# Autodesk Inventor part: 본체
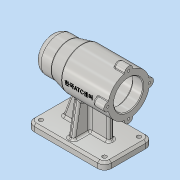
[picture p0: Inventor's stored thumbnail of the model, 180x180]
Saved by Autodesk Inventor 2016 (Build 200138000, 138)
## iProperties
Created: 2019-07
Part Number: 본체
Material: 알루미늄 6061
Document SubType Name: Modeling
Designer: Administrator
Density: 2.7 g/cm^3
Appearance: 알루미늄 - 평지
Mass: 644.388 g
Surface Area: 654.083 cm^2
Volume: 238.662 cm^3
Author: Administrator
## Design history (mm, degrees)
sketch "스케치1"
  geometry: L1 (56, 0)-(-56, 0); L2 (56, 0)-(56, 25); L3 (56, 25)-(31, 25); L4 (31, 25)-(11, 30); L5 (11, 30)-(-56, 30); L6 (-56, 30)-(-56, 21); L7 (-56, 21)-(-41, 21); L8 (-41, 21)-(-41, 24); L9 (-41, 24)-(13, 24); L10 (13, 24)-(13, 21); L11 (13, 21)-(25, 21); L12 (25, 21)-(25, 17.5); L13 (25, 17.5)-(43, 17.5); L14 (43, 17.5)-(43, 16); L15 (43, 16)-(47, 16); L16 (47, 16)-(47, 10.5); L17 (47, 10.5)-(50, 10.5); L18 (50, 10.5)-(50, 0); L19 (-56, 21)-(-56, 0); 2 further points
  constraints: 38 end point, 16 perpendicular, 1 coincident, 1 horizontal, 1 midpoint, 1 parallel, 1 point on line, 1 vertical
  dimensions: "d0" = 112 distance of L1.start L1.end; "d1" = 25 distance of L2.end L3.end; "d2" = 45 distance from line of L2 L4.end; "d3" = 60 diameter of L5 L1; "d4" = 50 diameter of L3 L1; "d5" = 3 distance between parallel lines of L18 L16; "d6" = 4 distance between parallel lines of L16 L14; "d7" = 18 distance between parallel lines of L12 L14; "d8" = 12 distance between parallel lines of L10 L12; "d9" = 54 distance between parallel lines of L8 L10; "d10" = 15 distance between parallel lines of L6 L8; "d11" = 42 diameter of L7 L1; "d12" = 48 diameter of L9 L1; "d13" = 21 diameter of L17 L1; "d14" = 32 diameter of L15 L1; "d15" = 35 diameter of L13 L1; "d16" = 42 diameter of L11 L1
revolve "회전1" sketch "스케치1" stored, may be unused: angle "d17" = 90 deg
node "작업 평면1"
sketch "스케치2"
  geometry: L1 (-56, -35)-(56, -35); L2 (56, -35)-(56, 35); L3 (56, 35)-(-56, 35); L4 (-56, 35)-(-56, -35); L5 (-56, -35)-(56, 35); L6 (56, -35)-(-56, 35); 1 further point
  constraints: 12 end point, 2 midpoint, 2 parallel, 1 horizontal, 1 perpendicular
  dimensions: "d19" = 112 distance of L3.end L2.end; "d20" = 70 distance of L2.end L1.end
extrude "돌출1" join sketch "스케치2" distance "d21" = 10; taper "d22" = 0 deg
sketch "스케치3"
  geometry: L1 (-56, -70)-(56, -70) reference; L2 (-31, -70)-(-31, -25.137); L3 (-31, -25.137)-(19.671, -25.137); L4 (19.671, -25.137)-(36, -70); L5 (56, -80)-(56, -70) reference; L6 (-56, -80)-(-56, -70) reference; 1 further point
  constraints: 6 end point, 2 point on line, 1 perpendicular, 1 vertical
  dimensions: "d23" = 20 distance from line of L5 L4.end; "d24" = 25 distance between parallel lines of L6 L2; "d25" = 110 deg angle of L1 L4; "d26" = 50.67136 distance of L2.end L3.end
extrude "돌출2" join sketch "스케치3" stored distance "d27" = 8; taper "d28" = 0 deg
sketch "스케치4"
  geometry: L1 (35, -70)-(-35, -70) reference; L2 (-28, -70)-(-19.654, -22.666); L3 (-35, -80)-(-35, -70) reference; 2 further points
  constraints: 2 end point, 1 point on line, 2 other
  dimensions: "d29" = 7 distance from line of L3 L2.start; "d30" = 100 deg angle of L1 L2
feature "리브1" sketch "스케치4" dims "d31" = 1, "d32" = 8, "d33" = 0, "d34" = 0, "d35" = 1, "d36" = 1
sketch "스케치5"
  geometry: C1 r 6 at (0, -30); 2 further points
  constraints: 2 vertical alignment, 1 centre point, 1 other
  dimensions: "d37" = 12 diameter of C1
extrude "돌출3" join sketch "스케치5" distance "d38" = 16; taper "d39" = 0 deg
sketch "스케치6"
  geometry: A1 r 6 centre (-30, 30) between (-29.4, 35.97) and (-29.4, 24.03) reference; A2 r 30 centre (0, 30) between (29.732, 34) and (29.732, 26) reference; 2 further points
  constraints: 1 horizontal alignment, 1 point on circle
hole "구멍1" sketch "스케치6" at (-30, 30) diameter "d43" = 3.242; stored, may be unused: countersink angle "d47" = 90 deg, drill point angle "d49" = 118 deg; dims "d44" = 8, "d45" = 4, "d46" = 2, "d48" = 11
node "작업 평면2"
sketch "스케치7"
  geometry: L1 (56, 36)-(56, 29.4) reference; 2 further points
  constraints: 1 horizontal alignment, 1 other
  dimensions: "d54" = 42 distance from line of L1 point (14, 0)
feature "엠보싱1" sketch "스케치7" dims "d0" = 112, "d1" = 25, "d2" = 45, "d3" = 60, "d4" = 50, "d5" = 3, "d6" = 4, "d7" = 18, "d8" = 12, "d9" = 54, "d10" = 15, "d11" = 42, "d12" = 48, "d13" = 21, "d14" = 32, "d15" = 35, "d16" = 42, "d17" = 90 deg, "d55" = 0.5, "d56" = 0
fillet "모깎기1" dims "d57" = 10
sketch "스케치8"
  geometry: A1 r 10 centre (-46, 25) between (-46, 35) and (-56, 25) reference; A2 r 10 centre (-46, -25) between (-56, -25) and (-46, -35) reference; A3 r 10 centre (46, -25) between (46, -35) and (56, -25) reference; A4 r 10 centre (46, 25) between (56, 25) and (46, 35) reference; 5 further points
  constraints: 4 coincident
hole "구멍2" sketch "스케치8" at (-46, -25), (-46, 25), (46, 25), (46, -25) diameter "d58" = 6; stored, may be unused: countersink angle "d62" = 90 deg, drill point angle "d64" = 0 deg; dims "d59" = 8, "d60" = 4, "d61" = 2, "d63" = 11
fillet "모깎기2" dims "d65" = 3
fillet "모깎기3" dims "d66" = 3, "d67" = 0.3
fillet "모깎기4" dims "d68" = 3, "d69" = 1
chamfer "모따기1" distance "d70" = 1; stored, may be unused: second distance "d71" = 2, angle "d72" = 45 deg
chamfer "모따기2" distance "d73" = 3; stored, may be unused: second distance "d74" = 2, angle "d75" = 45 deg
sketch "스케치9"
  geometry: L1 (150, -150)-(-150, -150); L2 (-150, -150)-(-150, 150); L3 (-150, 150)-(150, 150); L4 (150, 150)-(150, -150); L5 (150, -150)-(-150, 150); L6 (-150, -150)-(150, 150); 1 further point
  constraints: 12 end point, 2 midpoint, 2 parallel, 1 horizontal, 1 perpendicular
  dimensions: "d76" = 300 distance of L2.end L3.end; "d77" = 300 distance of L1.end L2.end
extrude "돌출4" cut sketch "스케치9" stored distance "d78" = 10; taper "d79" = 0 deg
node "솔리드1"
mirror "대칭1"
pattern_circular "원형 패턴1" dims angle "d41" = 360 deg
pattern_circular "원형 패턴2" dims angle "d51" = 360 deg
other parameters: "d53" = -45.25
